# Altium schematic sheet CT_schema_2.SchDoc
size 283 x 147 mm
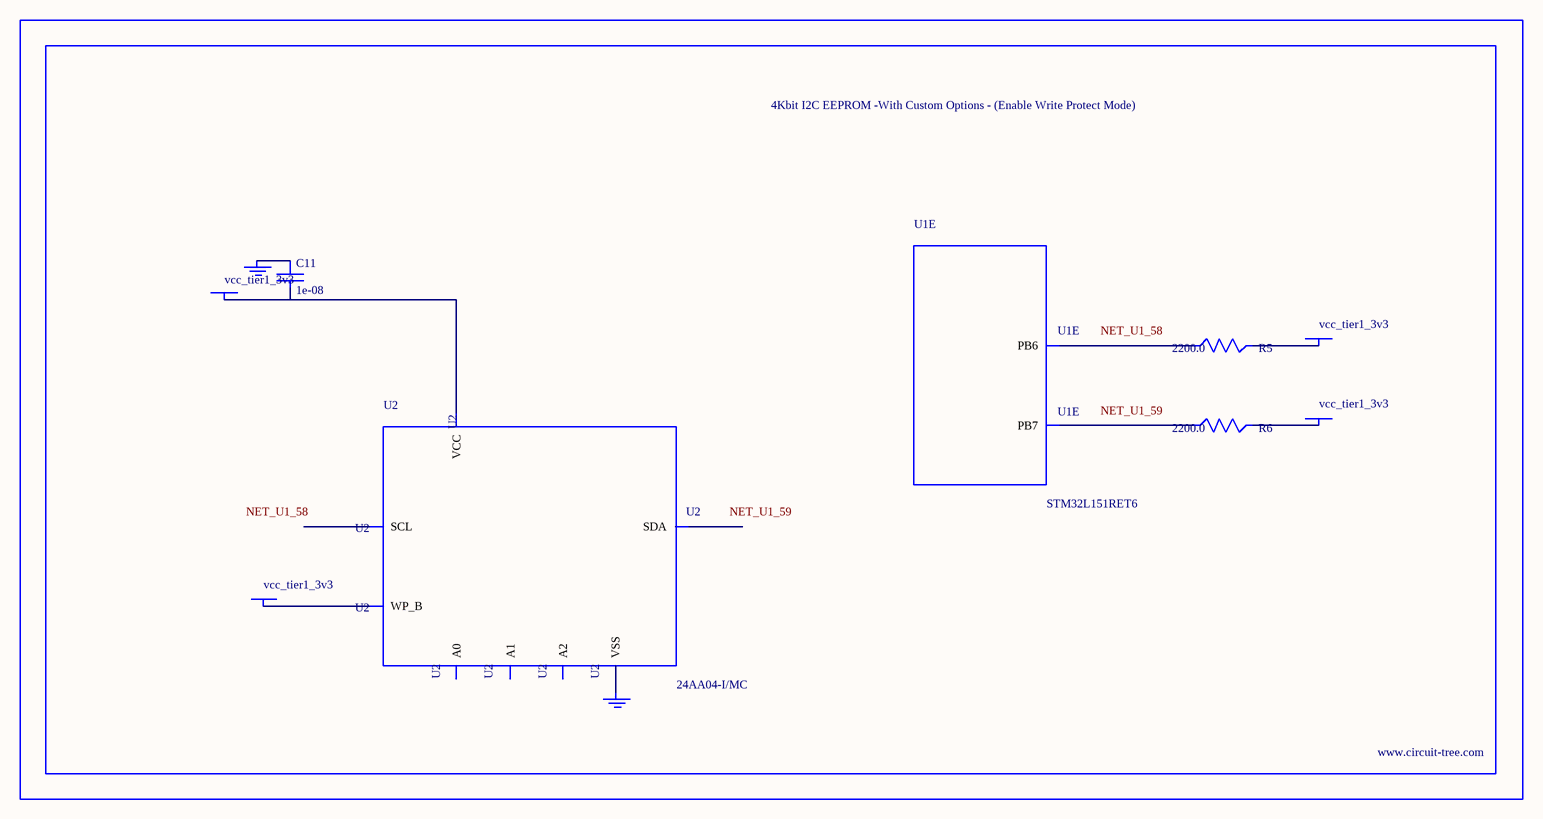
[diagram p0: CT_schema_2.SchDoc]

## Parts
BORDER1  (no value)
C11  1e-08  [C0402]
GND_INSTANCE_1_0  (no value)
GND_INSTANCE_1_1  (no value)
POWER_INSTANCE_1_0  vcc_tier1_3v3
POWER_INSTANCE_1_1  vcc_tier1_3v3
POWER_INSTANCE_1_2  vcc_tier1_3v3
POWER_INSTANCE_1_3  vcc_tier1_3v3
R5  2200.0  [R0603]
R6  2200.0  [R0603]
U1  STM32L151RET6  [LQFP64]  (part E of 7)
U2  24AA04-I/MC  [TDFN-8/6MM]

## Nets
NetC11_1: C11.1 GND_INSTANCE_1_0.0(GND)
NetC11_2: C11.2 POWER_INSTANCE_1_1.0(PWR) U2.8(VCC)
NetGND_INSTANCE_1_1_0: GND_INSTANCE_1_1.0(GND) U2.4(VSS)
NetPOWER_INSTANCE_1_0_0: POWER_INSTANCE_1_0.0(PWR) U2.7(WP_B)
NetPOWER_INSTANCE_1_2_0: POWER_INSTANCE_1_2.0(PWR) R5.2
NetPOWER_INSTANCE_1_3_0: POWER_INSTANCE_1_3.0(PWR) R6.2
NetR5_1: R5.1 U1.58(PB6)
NetR6_1: R6.1 U1.59(PB7)

Not connected (* = marked no-connect by the designer): U2 1(A0) 2(A1) 3(A2) 5(SDA) 6(SCL)

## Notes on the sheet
- Labels drawn without touching a wire or pin: NET_U1_58, NET_U1_59

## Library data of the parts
BORDER1 = BORDER_PAGE1
C11 = C0402C103K3RAC
GND_INSTANCE_1_0 GND_INSTANCE_1_1 = GND
POWER_INSTANCE_1_0-POWER_INSTANCE_1_3 = PWR
R5 R6 = RC0603JR-072K2L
